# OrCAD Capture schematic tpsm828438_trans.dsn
size E
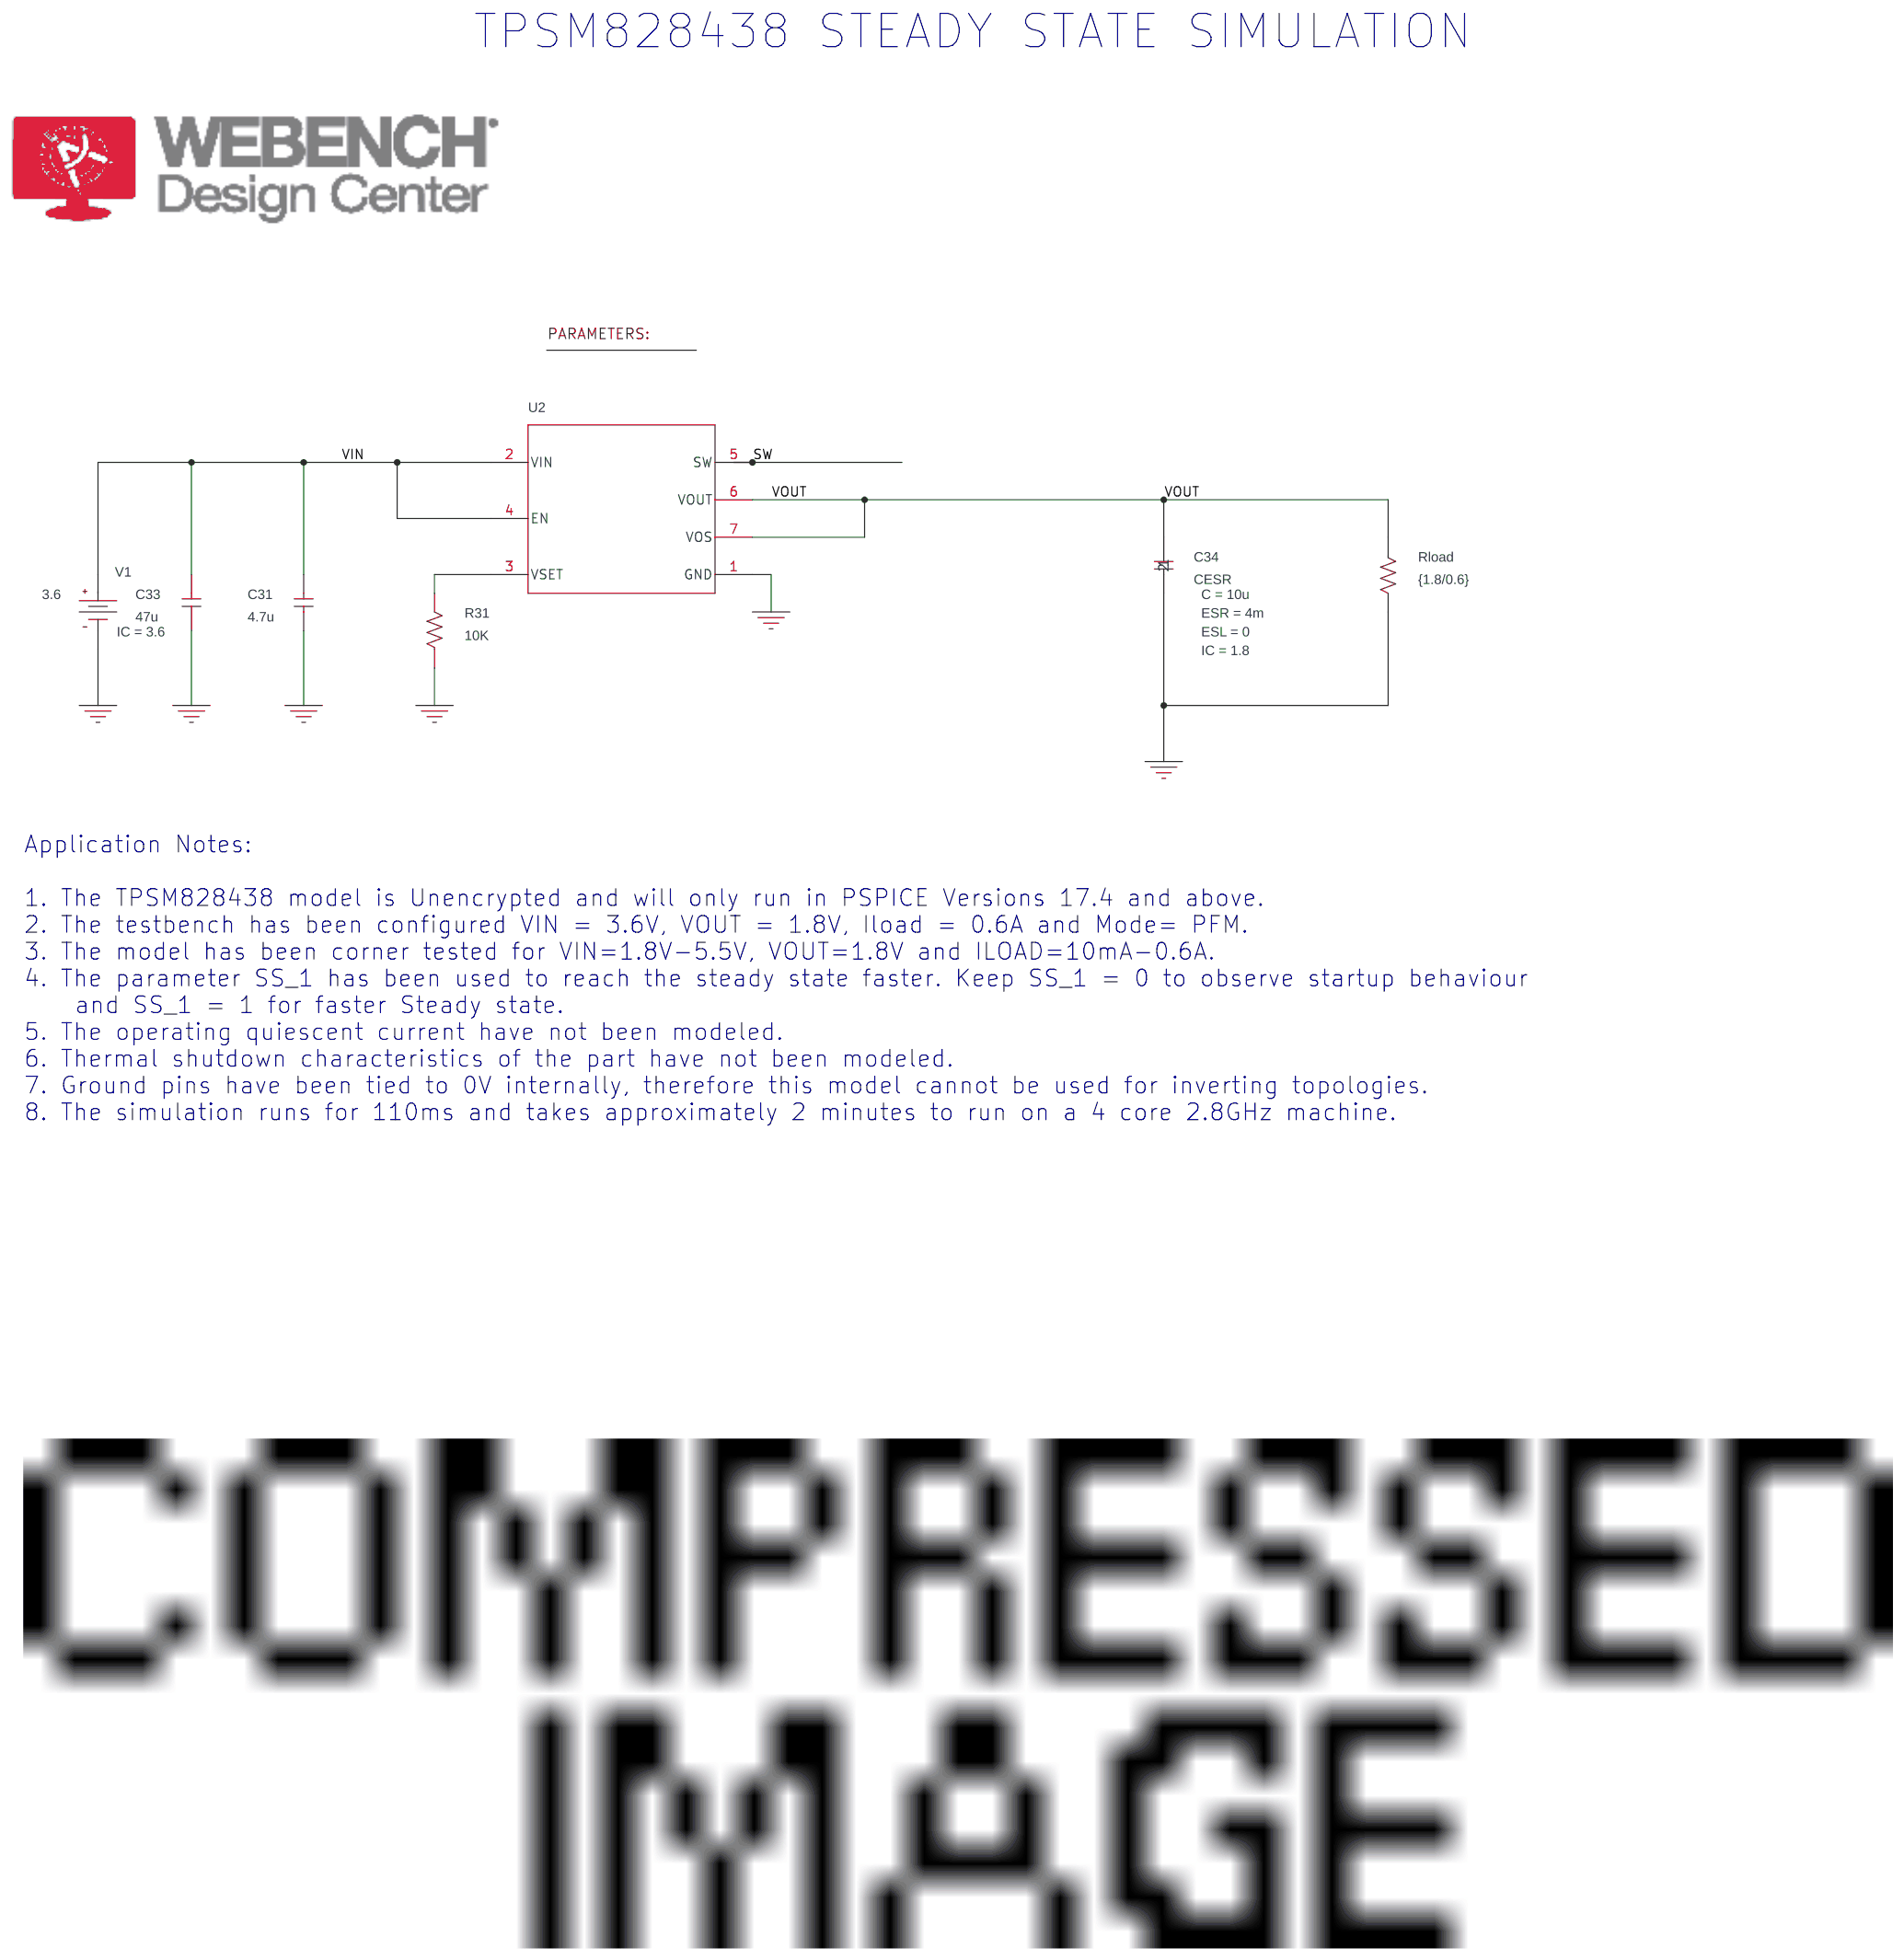
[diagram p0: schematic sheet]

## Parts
1  PARAM
C31  4.7u  [RAD/CK05]
C33  47u  [RAD/CK05]
C34  CESR
R31  10K  [AX/RC05]
Rload  {1.8/0.6}  [AX/RC05]
U2  Value  [VCF0007A-MFG]
V1  VDC

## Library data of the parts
1 = PARAM: VOUT_1: 1.8
C31 C33 = C: IC: 3.6
C34 = CESR: C: 10u; ESL: 0; ESR: 4m; IC: 1.8; PSpiceTemplate: X^@REFDES %1 %2 @MODEL PARAMS: ?C|C=@C||C=10U| ?ESR|ESR=@ESR||ESR=2M| ?ESL|ESL=@ESL||ESL=1N| ?IC|IC=@IC||IC=0|
R31 Rload = R
U2 = TPSM828438VCF_TRANS
V1 = VDC: DC: 3.6

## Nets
VIN: C31.2 C33.2 U2.2(VIN) U2.4(EN) V1.0(+)
0: C31.1 C33.1 C34.2 R31.1 Rload.2 U2.1(GND) V1.1(-)
SW: U2.5(SW)
VOUT: C34.1 Rload.1 U2.6(VOUT) U2.7(VOS)
N00506: R31.2 U2.3(VSET)

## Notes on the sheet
- TPSM828438 STEADY STATE SIMULATION
- Application Notes:
  1. The TPSM828438 model is Unencrypted and will only run in PSPICE Versions 17.4 and above.
  2. The testbench has been configured VIN = 3.6V, VOUT = 1.8V, Iload = 0.6A and Mode= PFM.
  3. The model has been corner tested for VIN=1.8V-5.5V, VOUT=1.8V and ILOAD=10mA-0.6A.
  4. The parameter SS_1 has been used to reach the steady state faster. Keep SS_1 = 0 to observe startup behaviour
      and SS_1 = 1 for faster Steady state.
  5. The operating quiescent current have not been modeled.
  6. Thermal shutdown characteristics of the part have not been modeled.
  7. Ground pins have been tied to 0V internally, therefore this model cannot be used for inverting topologies.
  8. The simulation runs for 110ms and takes approximately 2 minutes to run on a 4 core 2.8GHz machine.
